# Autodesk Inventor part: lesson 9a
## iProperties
Author: E. MOSS
Created: 2001-08
Part Number: lesson 9a
Document SubType Name: Sheet Metal
Designer: E. MOSS
Control State: 0
Master: False
Checked Out: False
PropertySet Name: Design Tracking Control
Length Units: 11272
Angle Units: 11279
Time Units: 11290
Mass Units: 11286
Shininess: 3
Angle Display Precision: 2
Document Length Units: 11272
Document Angle Units: 11286
Document Time Units: 11279
Document Mass Units: 11290
Document Length Units Precision: 3
Document Angle Units Precision: 2
Compacted: False
PropertySet Name: _Private Model Information
Density: 0.0
Volumn: 0.0
Area: 0.0
PropertySet Name: Model Information
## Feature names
1. Plate1
2. Bend1
3. Plate2
4. Bend2
5. Cut1
